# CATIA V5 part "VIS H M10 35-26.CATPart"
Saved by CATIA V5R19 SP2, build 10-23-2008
Part number: VIS H M10 35-26
Bounding box of the stored display mesh (mm): x -6.4 to 35, y -9.815 to 9.815, z -8.5 to 8.5
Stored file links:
  D:\SCHOOL\FRANCE\BANC_POUTRE_EN_MOUSSE\VIS H M10 35-26.CATPart
  C:\Program Files\DS\B19\intel_a\reffiles\standard\MetricThickPitch.txt
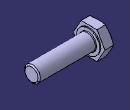
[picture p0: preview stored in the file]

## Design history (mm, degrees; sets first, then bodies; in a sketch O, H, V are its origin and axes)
Set1
  Point1: (0, 0, 0)
  Point2: (1, 0, 0)
  Point3: (0, 1, 0)
  Plane1: type 3Points, Element1 Point1, Element2 Point2, Element3 Point3
  Point4: (0, 0, 0)
  Point5: (0, 0, -1)
  Point6: (0, 1, 0)
  Plane2: type 3Points, Element1 Point4, Element2 Point5, Element3 Point6
Body1 (main body)
  Sketch1 on Plane1, origin (0, 0, 0), H (1, 0, 0), V (0, 1, 0)
    point P1 (-6.4, 0)
    point P2 (-6.4, 8.5)
    line L1 (-6.4, 0) -> (-6.4, 8.5)
    point P3 (-6.4, 8.5)
    point P4 (-4.5438, 13.6)
    line L2 (-6.4, 8.5) -> (-4.5438, 13.6)
    point P5 (-4.5438, 13.6)
    point P6 (-0.6, 13.6)
    line L3 (-4.5438, 13.6) -> (-0.6, 13.6)
    point P7 (-0.6, 13.6)
    point P8 (-0.6, 7.315)
    line L4 (-0.6, 13.6) -> (-0.6, 7.315)
    point P9 (-0.6, 7.315)
    point P10 (0, 7.315)
    line L5 (-0.6, 7.315) -> (0, 7.315)
    point P11 (0, 7.315)
    point P12 (0, 5.4)
    line L6 (0, 7.315) -> (0, 5.4)
    arc A1 centre (0.4, 5.4) radius 0.4 from (0, 5.4) to (0.4, 5) ccw
    point P13 (0.4, 5)
    line L7 (0.4, 5) -> (34.3558, 5)
    line L8 (34.3558, 5) -> (35, 4.08)
    point P14 (40, 0)
    line L9 (35, 4.08) -> (35, 0)
    point P15 (40, 0)
    point P16 (-6.4, 0)
    line L10 (35, 0) -> (-6.4, 0)
    point P17 (40, 0)
    point P18 (-6.4, 0)
    axis line L11 (40, 0) -> (-6.4, 0)
    point P19 (-6.4, 0)
    point P20 (-6.4, 8.5)
    point P21 (-6.4, 8.5)
    point P22 (-4.5438, 13.6)
    point P23 (-4.5438, 13.6)
    point P24 (-0.6, 13.6)
    point P25 (-0.6, 13.6)
    point P26 (-0.6, 7.315)
    point P27 (-0.6, 7.315)
    point P28 (0, 7.315)
    point P29 (0, 7.315)
    point P30 (0, 5.4)
    point P31 (0, 5.4)
    point P32 (0.4, 5)
    point P33 (0.4, 5)
    point P34 (34.3558, 5)
    point P35 (34.3558, 5)
    point P36 (35, 4.08)
    point P37 (35, 4.08)
    point P38 (35, 0)
    point P39 (35, 0)
    point P40 (-6.4, 0)
    distance L9 L6 = 35
    coincidence: P19 P40, P20 P21, P22 P23, P24 P25, P26 P27, P28 P29, P30 P31, P32 P33, P34 P35, P36 P37, P38 P39
    tangency: L7 A1, A1 L6
  Shaft1: profile Sketch1, axis Sketch1.L11, angle 0, second angle 360
  Sketch2 on Plane2, origin (0, 0, 0), H (0, 0, -1), V (0, 1, 0)
    point P1 (-17, 17)
    point P2 (-17, -17)
    line L1 (-17, 17) -> (-17, -17)
    point P3 (-17, -17)
    point P4 (17, -17)
    line L2 (-17, -17) -> (17, -17)
    point P5 (17, -17)
    point P6 (17, 17)
    line L3 (17, -17) -> (17, 17)
    point P7 (17, 17)
    point P8 (-17, 17)
    line L4 (17, 17) -> (-17, 17)
    point P9 (-8.5, 4.9075)
    point P10 (-8.5, -4.9075)
    line L5 (-8.5, 4.9075) -> (-8.5, -4.9075)
    point P11 (-8.5, -4.9075)
    point P12 (0, -9.815)
    line L6 (-8.5, -4.9075) -> (0, -9.815)
    point P13 (0, -9.815)
    point P14 (8.5, -4.9075)
    line L7 (0, -9.815) -> (8.5, -4.9075)
    point P15 (8.5, -4.9075)
    point P16 (8.5, 4.9075)
    line L8 (8.5, -4.9075) -> (8.5, 4.9075)
    point P17 (8.5, 4.9075)
    point P18 (0, 9.815)
    line L9 (8.5, 4.9075) -> (0, 9.815)
    point P19 (0, 9.815)
    point P20 (-8.5, 4.9075)
    line L10 (0, 9.815) -> (-8.5, 4.9075)
    point P21 (-17, 17)
    point P22 (-17, -17)
    point P23 (-17, -17)
    point P24 (17, -17)
    point P25 (17, -17)
    point P26 (17, 17)
    point P27 (17, 17)
    point P28 (-17, 17)
    point P29 (-8.5, 4.9075)
    point P30 (-8.5, -4.9075)
    point P31 (-8.5, -4.9075)
    point P32 (0, -9.815)
    point P33 (0, -9.815)
    point P34 (8.5, -4.9075)
    point P35 (8.5, -4.9075)
    point P36 (8.5, 4.9075)
    point P37 (8.5, 4.9075)
    point P38 (0, 9.815)
    point P39 (0, 9.815)
    point P40 (-8.5, 4.9075)
    coincidence: P21 P28, P22 P23, P24 P25, P26 P27, P29 P40, P30 P31, P32 P33, P34 P35, P36 P37, P38 P39
  Pocket1: profile Sketch2, direction (-1, 0, 0), length 6.4
  Thread1: "M10", diameter 10, depth 26, pitch 1.5, on face of Shaft1 from Sketch1.L7, from face of Shaft1 from Sketch1.L9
